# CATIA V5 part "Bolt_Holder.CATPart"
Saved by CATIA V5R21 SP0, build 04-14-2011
Part number: Bolt_Holder
Bounding box of the stored display mesh (mm): x -89 to 89, y -7 to 7, z 0 to 2.8
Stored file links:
  C:\Users\Pouria\Desktop\Box\Assembled\Bolt_Holder.CATPart
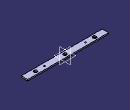
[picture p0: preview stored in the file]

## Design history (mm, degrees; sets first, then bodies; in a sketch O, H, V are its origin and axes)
Body1 (main body)
  Sketch1 on xy-plane, origin (0, 0, 0), H (1, 0, 0), V (0, 1, 0)
    line L1 (89, 7) -> (89, -7)
    line L2 (89, -7) -> (-89, -7)
    line L3 (-89, -7) -> (-89, 7)
    line L4 (-89, 7) -> (89, 7)
    circle A1 centre (45, 0) radius 1.5
    point P5 (45, 0)
    circle A2 centre (-45, 0) radius 1.5
    point P6 (-45, 0)
    point P7 (65, 0)
    point P8 (67.0207, 3.5)
    point P9 (62.9793, 3.5)
    point P10 (60.9585, 0)
    point P11 (62.9793, -3.5)
    point P12 (67.0207, -3.5)
    point P13 (69.0415, 0)
    point P14 (65, 3.5)
    line L5 (67.0207, 3.5) -> (62.9793, 3.5)
    line L6 (62.9793, 3.5) -> (60.9585, 0)
    line L7 (60.9585, 0) -> (62.9793, -3.5)
    line L8 (62.9793, -3.5) -> (67.0207, -3.5)
    line L9 (67.0207, -3.5) -> (69.0415, 0)
    line L10 (69.0415, 0) -> (67.0207, 3.5)
    construction line L11 (65, 0) -> (65, 3.5)
    construction circle A3 centre (65, 0) radius 4.0415
    construction arc A4 centre (67.0207, -3.5) radius 4.0415 from (62.9793, -3.5) to (69.0415, 0) cw
    construction arc A5 centre (62.9793, 3.5) radius 4.0415 from (60.9585, 0) to (67.0207, 3.5) ccw
    point P15 (-65, 0)
    point P16 (-62.9793, 3.5)
    point P17 (-67.0207, 3.5)
    point P18 (-69.0415, 0)
    point P19 (-67.0207, -3.5)
    point P20 (-62.9793, -3.5)
    point P21 (-60.9585, 0)
    point P22 (-65, 3.5)
    line L12 (-62.9793, 3.5) -> (-67.0207, 3.5)
    line L13 (-67.0207, 3.5) -> (-69.0415, 0)
    line L14 (-69.0415, 0) -> (-67.0207, -3.5)
    line L15 (-67.0207, -3.5) -> (-62.9793, -3.5)
    line L16 (-62.9793, -3.5) -> (-60.9585, 0)
    line L17 (-60.9585, 0) -> (-62.9793, 3.5)
    construction line L18 (-65, 0) -> (-65, 3.5)
    construction circle A6 centre (-65, 0) radius 4.0415
    construction arc A7 centre (-62.9793, -3.5) radius 4.0415 from (-67.0207, -3.5) to (-60.9585, 0) cw
    construction arc A8 centre (-67.0207, 3.5) radius 4.0415 from (-69.0415, 0) to (-62.9793, 3.5) ccw
    point P23 (4.0415, 0)
    point P24 (2.0207, 3.5)
    point P25 (-2.0207, 3.5)
    point P26 (-4.0415, 0)
    point P27 (-2.0207, -3.5)
    point P28 (2.0207, -3.5)
    point P29 (3.0311, 1.75)
    line L19 (4.0415, 0) -> (2.0207, 3.5)
    line L20 (2.0207, 3.5) -> (-2.0207, 3.5)
    line L21 (-2.0207, 3.5) -> (-4.0415, 0)
    line L22 (-4.0415, 0) -> (-2.0207, -3.5)
    line L23 (-2.0207, -3.5) -> (2.0207, -3.5)
    line L24 (2.0207, -3.5) -> (4.0415, 0)
    construction line L25 (0, 0) -> (3.0311, 1.75)
    construction circle A9 centre (0, 0) radius 4.0415
    construction arc A10 centre (-2.0207, -3.5) radius 4.0415 from (-4.0415, 0) to (2.0207, -3.5) cw
    construction arc A11 centre (2.0207, 3.5) radius 4.0415 from (-2.0207, 3.5) to (4.0415, 0) ccw
    length L4 = 178
    length L1 = 14
    distance P6 L3 = 44
    distance P5 L1 = 44
    radius A1 = 1.5
    radius A2 = 1.5
    distance L8 L5 = 7
    distance L15 L12 = 7
    distance P7 L1 = 24
    distance P15 L3 = 24
    vertical: L1 V, L3 V, L11 V, L18 V
    horizontal: L2 H, L4 H, L5 H, L12 H, L20 H
    equidistance: L1 L3 O, L2 L4 O
    coincidence: P5 H, P6 H, P7 H, A3 P8, A3 P9, A3 P10, A3 P11, A3 P12, A3 P13, A4 P7, A5 P7, P15 H, A6 P16, A6 P17, A6 P18, A6 P19, A6 P20, A6 P21, A7 P15, A8 P15, A9 P23, A9 P24, A9 P25, A9 P26, A9 P27, A9 P28, A10 O, A11 O, L20 L5
    midpoint: P14 L5, P22 L12, P29 L19
    parallelism: L19 L22
  Pad1: profile Sketch1, direction (0, 0, 1), length 2.8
